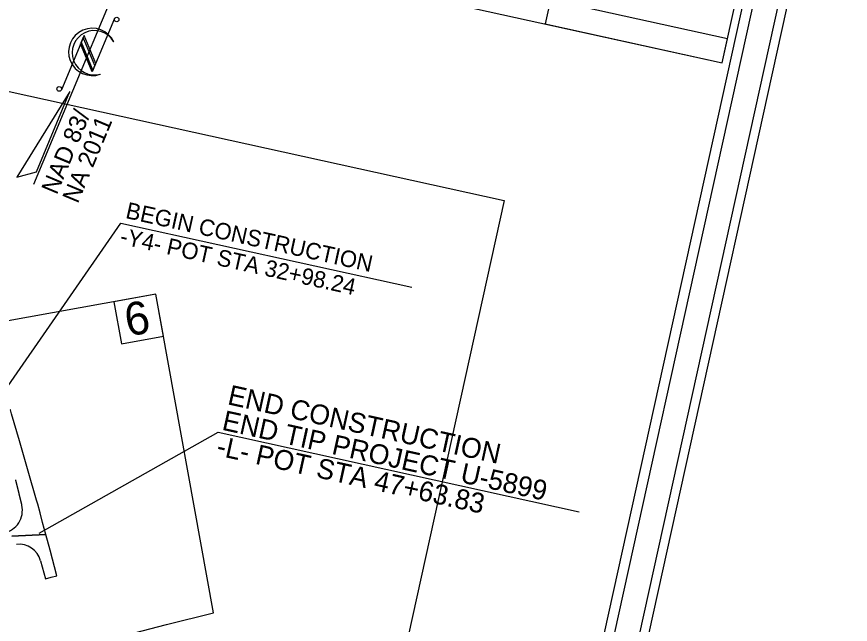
# Model space of a CAD drawing. Extents: x 1609449 to 1623942, y 894240 to 902860.
# Drawn here: x 1621409 to 1623942, y 897935 to 899782 of the extents above; entities that cross this region are included whole.
import ezdxf

# ---------------------------------------------------------------- set-up
doc = ezdxf.new("R2010")
doc.units = 0
for name, color, linetype in [('Old_Level_1', 7, 'Continuous'), ('Prop Horizontal Alignment Station Label', 7, 'Continuous'), ('Prop Shade Light', 7, 'Continuous'), ('Scratch_Level_0', 7, 'Continuous'), ('Scratch_Level_1', 7, 'Continuous'), ('Sheet North Arrow CELL', 7, 'Continuous'), ('Sheet Plot Border Inside CELL', 7, 'Continuous'), ('Sheet Plot Border Outside CELL', 7, 'Continuous'), ('Sheet Title CELL', 7, 'Continuous')]:
    doc.layers.add(name, color=color, linetype=linetype)

msp = doc.modelspace()

# ---------------------------------------------------------------- linework, layer by layer
at = {"layer": 'Old_Level_1'}
for points in [[(1620396.2, 898448.3), (1620661.8, 898448.3), (1620661.8, 897662.4), (1621336.9, 897793.5), (1621466.5, 897830.2), (1621864, 897934.4), (1622007.2, 897969.4), (1621831.8, 898938.5), (1620355.8, 898671.4)], [(1621831.8, 898938.5), (1621704, 898915.4), (1621727.2, 898787.1), (1621855.1, 898810.2)]]:
    msp.add_lwpolyline(points, close=True, dxfattribs=at)
at = {"layer": 'Prop Horizontal Alignment Station Label'}
for p, q in [((1621364.7, 898632.9), (1621724.9, 899154)), ((1621724.9, 899154), (1622609.8, 898959.1)), ((1621477.4, 898211.6), (1622021.1, 898518.3)), ((1622021.1, 898518.3), (1623118, 898276.7))]:
    msp.add_line(p, q, dxfattribs=at)
at = {"layer": 'Prop Shade Light'}
for p, q in [((1621393.9, 898202.3), (1621497.1, 898207.8)), ((1621497.1, 898207.8), (1621393.9, 898202.3)), ((1621393.9, 898202.3), (1621497.1, 898207.8)), ((1621510, 898159.7), (1621497.1, 898207.8)), ((1621530.7, 898082.4), (1621510, 898159.7)), ((1621481.2, 898127.7), (1621495.9, 898073.1))]:
    msp.add_line(p, q, dxfattribs=at)
for points in [[(1621472.6, 898299.5), (1621468.8, 898312.4), (1621443.5, 898400), (1621426.9, 898457.3), (1621416.7, 898492.7), (1621393.1, 898574.2), (1621389.6, 898586.2), (1621389.2, 898587.7)], [(1621497.1, 898207.8), (1621487.3, 898244.2), (1621479.5, 898273.6), (1621472.6, 898299.5)], [(1621495.9, 898073.1), (1621513.3, 898077.8), (1621530.7, 898082.4)]]:
    msp.add_lwpolyline(points, dxfattribs=at)
for centre, start, end in [((1621357.9, 898280.1), 280.2581, 13.8394), ((1621415.6, 898110.2), 14.985, 96.6994)]:
    msp.add_arc(centre, 68, start, end, dxfattribs=at)
msp.add_spline([(1621404.9, 898373.4), (1621405.1, 898372.8), (1621405.3, 898371.9), (1621405.5, 898371.1), (1621405.7, 898370.2), (1621405.9, 898369.3), (1621406.1, 898368.4), (1621406.4, 898367.6), (1621406.6, 898366.7), (1621406.8, 898365.8), (1621407, 898364.9), (1621407.2, 898364.1), (1621407.4, 898363.2), (1621407.6, 898362.3), (1621407.9, 898361.4), (1621408.1, 898360.6), (1621408.3, 898359.7), (1621408.5, 898358.8), (1621408.7, 898357.9), (1621408.9, 898357.1), (1621409.2, 898356.2), (1621409.4, 898355.3), (1621409.6, 898354.4), (1621409.8, 898353.6), (1621410, 898352.7), (1621410.2, 898351.8)], degree=3, dxfattribs=at)
for points in [[(1621410.2, 898351.8), (1621410.3, 898351.5), (1621410.4, 898351.2), (1621410.4, 898350.9), (1621410.5, 898350.6), (1621410.6, 898350.4), (1621410.7, 898350.1), (1621410.7, 898349.8), (1621410.8, 898349.5), (1621410.9, 898349.2), (1621410.9, 898348.9), (1621411, 898348.6), (1621411.1, 898348.3), (1621411.2, 898348), (1621411.2, 898347.7), (1621411.3, 898347.4), (1621411.4, 898347.2), (1621411.5, 898346.9), (1621411.5, 898346.6), (1621411.6, 898346.3), (1621411.7, 898346), (1621411.7, 898345.7), (1621411.8, 898345.4), (1621411.9, 898345.1), (1621412, 898344.8), (1621412, 898344.5), (1621412.1, 898344.2), (1621412.2, 898343.9), (1621412.2, 898343.7), (1621412.3, 898343.4), (1621412.4, 898343.1), (1621412.5, 898342.8), (1621412.5, 898342.5), (1621412.6, 898342.2), (1621412.7, 898341.9), (1621412.7, 898341.6), (1621412.8, 898341.3), (1621412.9, 898341), (1621413, 898340.7), (1621413, 898340.4), (1621413.1, 898340.2), (1621413.2, 898339.9), (1621413.2, 898339.6), (1621413.3, 898339.3), (1621413.4, 898339), (1621413.5, 898338.7), (1621413.5, 898338.4), (1621413.6, 898338.1), (1621413.7, 898337.8), (1621413.8, 898337.5), (1621413.8, 898337.2), (1621413.9, 898336.9), (1621414, 898336.7), (1621414, 898336.4), (1621414.1, 898336.1), (1621414.2, 898335.8), (1621414.3, 898335.5), (1621414.3, 898335.2), (1621414.4, 898334.9), (1621414.5, 898334.6), (1621414.5, 898334.3), (1621414.6, 898334), (1621414.7, 898333.7), (1621414.8, 898333.4), (1621414.8, 898333.2), (1621414.9, 898332.9), (1621415, 898332.6), (1621415, 898332.3), (1621415.1, 898332), (1621415.2, 898331.7), (1621415.3, 898331.4), (1621415.3, 898331.1), (1621415.4, 898330.8), (1621415.5, 898330.5), (1621415.5, 898330.2), (1621415.6, 898329.9), (1621415.7, 898329.7), (1621415.8, 898329.4), (1621415.8, 898329.1), (1621415.9, 898328.8), (1621416, 898328.5), (1621416.1, 898328.2), (1621416.1, 898327.9), (1621416.2, 898327.6), (1621416.3, 898327.3), (1621416.3, 898327), (1621416.4, 898326.7), (1621416.5, 898326.4), (1621416.6, 898326.2), (1621416.6, 898325.9), (1621416.7, 898325.6), (1621416.8, 898325.3), (1621416.8, 898325), (1621416.9, 898324.7), (1621417, 898324.5), (1621417, 898324.3), (1621417.1, 898324.1)], [(1621417.1, 898324.1), (1621417.1, 898324), (1621417.1, 898323.9), (1621417.1, 898323.8), (1621417.2, 898323.5), (1621417.3, 898323.2), (1621417.3, 898322.9), (1621417.4, 898322.7), (1621417.5, 898322.4), (1621417.6, 898322.1), (1621417.6, 898321.8), (1621417.7, 898321.5), (1621417.8, 898321.2), (1621417.8, 898320.9), (1621417.9, 898320.6), (1621418, 898320.3), (1621418.1, 898320), (1621418.1, 898319.7), (1621418.2, 898319.4), (1621418.3, 898319.2), (1621418.3, 898318.9), (1621418.4, 898318.6), (1621418.5, 898318.3), (1621418.6, 898318), (1621418.6, 898317.7), (1621418.7, 898317.4), (1621418.8, 898317.1), (1621418.9, 898316.8), (1621418.9, 898316.5), (1621419, 898316.2), (1621419.1, 898315.9), (1621419.1, 898315.7), (1621419.2, 898315.4), (1621419.3, 898315.1), (1621419.4, 898314.8), (1621419.4, 898314.5), (1621419.5, 898314.2), (1621419.6, 898313.9), (1621419.6, 898313.6), (1621419.7, 898313.3), (1621419.8, 898313), (1621419.9, 898312.7), (1621419.9, 898312.4), (1621420, 898312.2), (1621420.1, 898311.9), (1621420.1, 898311.6), (1621420.2, 898311.3), (1621420.3, 898311), (1621420.4, 898310.7), (1621420.4, 898310.4), (1621420.5, 898310.1), (1621420.6, 898309.8), (1621420.6, 898309.5), (1621420.7, 898309.2), (1621420.8, 898308.9), (1621420.9, 898308.7), (1621420.9, 898308.4), (1621421, 898308.1), (1621421.1, 898307.8), (1621421.2, 898307.5), (1621421.2, 898307.2), (1621421.3, 898306.9), (1621421.4, 898306.6), (1621421.4, 898306.3), (1621421.5, 898306), (1621421.6, 898305.7), (1621421.7, 898305.4), (1621421.7, 898305.2), (1621421.8, 898304.9), (1621421.9, 898304.6), (1621421.9, 898304.3), (1621422, 898304), (1621422.1, 898303.7), (1621422.2, 898303.4), (1621422.2, 898303.1), (1621422.3, 898302.8), (1621422.4, 898302.5), (1621422.4, 898302.2), (1621422.5, 898301.9), (1621422.6, 898301.7), (1621422.7, 898301.4), (1621422.7, 898301.1), (1621422.8, 898300.8), (1621422.9, 898300.5), (1621422.9, 898300.2), (1621423, 898299.9), (1621423.1, 898299.6), (1621423.2, 898299.3), (1621423.2, 898299), (1621423.3, 898298.7), (1621423.4, 898298.4), (1621423.5, 898298.2), (1621423.5, 898297.9), (1621423.6, 898297.6), (1621423.7, 898297.3), (1621423.7, 898297), (1621423.8, 898296.7), (1621423.8, 898296.6), (1621423.9, 898296.5), (1621423.9, 898296.4)]]:
    msp.add_open_spline(points, degree=3, dxfattribs=at)
at = {"layer": 'Scratch_Level_0'}
msp.add_lwpolyline([(1615937.3, 900755.3), (1622890.3, 899223.5), (1622107.1, 895668.6), (1615154.1, 897200.4)], close=True, dxfattribs=at)
at = {"layer": 'Scratch_Level_1'}
msp.add_lwpolyline([(1615937.3, 900755.3), (1622890.3, 899223.5), (1622107.1, 895668.6), (1615154.1, 897200.4)], close=True, dxfattribs=at)
at = {"layer": 'Sheet North Arrow CELL'}
for p, q in [((1621460.5, 899272.5), (1621791.4, 900064.2)), ((1621706.1, 899776.2), (1621638.2, 899613.7)), ((1621613.5, 899724.9), (1621544.5, 899559.7)), ((1621648.7, 899639.1), (1621613.5, 899724.9)), ((1621638.2, 899613.7), (1621602.9, 899699.6)), ((1621611, 899718.9), (1621604.8, 899704.1)), ((1621640, 899618.2), (1621604.8, 899704.1)), ((1621604.8, 899704.1), (1621640, 899618.2)), ((1621646.2, 899633.1), (1621611, 899718.9)), ((1621703.2, 899706.3), (1621703.8, 899705.3)), ((1621640, 899618.2), (1621646.2, 899633.1))]:
    msp.add_line(p, q, dxfattribs=at)
msp.add_lwpolyline([(1621570.6, 899554.1), (1621409.2, 899294), (1621468.8, 899310.5)], close=True, dxfattribs=at)
for centre in [(1621712.5, 899773.4), (1621537.9, 899562.2)]:
    msp.add_circle(centre, 7, dxfattribs=at)
for centre, radius, start, end in [((1621638.5, 899674.7), 72.1, 25.1555, 289.7096), ((1621644.9, 899672.1), 67.6, 30.4106, 285.9442)]:
    msp.add_arc(centre, radius, start, end, dxfattribs=at)
at = {"layer": 'Sheet Plot Border Inside CELL'}
msp.add_lwpolyline([(1612759.9, 896529.1), (1622524.8, 894377.7), (1623886.8, 900560.1), (1614122, 902711.4)], close=True, dxfattribs=at)
at = {"layer": 'Sheet Plot Border Outside CELL'}
msp.add_lwpolyline([(1623942.2, 900685.8), (1614074.8, 902859.7), (1612654.8, 896414.4), (1622522.2, 894240.5)], close=True, dxfattribs=at)
at = {"layer": 'Sheet Title CELL'}
for points in [[(1623160.2, 900418.9), (1623015, 899759.7), (1623552.3, 899641.3), (1623745.9, 900520.2)], [(1622467.7, 894467.5), (1623797.4, 900502.7)], [(1622683.7, 895587.2), (1623761.6, 900479.9)], [(1621940.9, 899996.3), (1623552.3, 899641.3), (1623568.4, 899714.5), (1621957.1, 900069.6)]]:
    msp.add_lwpolyline(points, dxfattribs=at)

# ---------------------------------------------------------------- texts
at = {"layer": 'Old_Level_1'}
msp.add_text('6', height=100, rotation=10.2599, dxfattribs=at).set_placement((1621746.5, 898809.3))
at = {"layer": 'Prop Horizontal Alignment Station Label'}
for s, height, p in [('BEGIN CONSTRUCTION', 50, (1621737, 899170)), ('-Y4- POT STA 32+98.24', 50, (1621719.7, 899091.9)), ('END CONSTRUCTION', 60.5, (1622046.8, 898603.9)), ('END TIP PROJECT U-5899', 60.5, (1622029.7, 898526.5)), ('-L- POT STA 47+63.83', 60.5, (1622012.7, 898449))]:
    msp.add_text(s, height=height, rotation=347.5755, dxfattribs=at).set_placement(p)
at = {"layer": 'Sheet North Arrow CELL'}
for s, p in [('NAD 83/', (1621530.4, 899238.2)), ('NA 2011', (1621594.3, 899211.5))]:
    msp.add_text(s, height=52.8, rotation=67.3155, dxfattribs=at).set_placement(p)

doc.saveas('drawing.dxf')
